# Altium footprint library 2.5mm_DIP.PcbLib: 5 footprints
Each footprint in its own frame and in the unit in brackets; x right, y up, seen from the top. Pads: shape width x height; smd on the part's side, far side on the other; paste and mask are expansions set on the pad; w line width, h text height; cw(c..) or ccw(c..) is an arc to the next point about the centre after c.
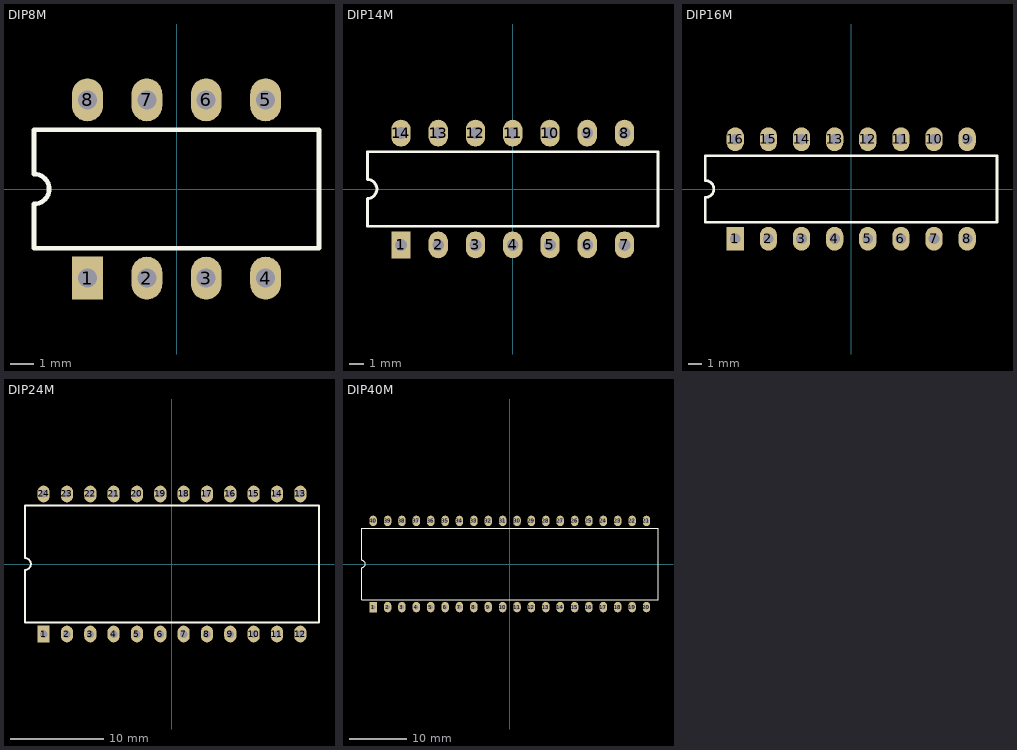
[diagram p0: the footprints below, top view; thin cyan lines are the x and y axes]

## DIP8M [mm] "2.5mm grid"
height 5
pads (8):
  rect 1.3x1.8 hole 0.8: 1(-3.75,-3.75)
  rrect100% 1.3x1.8 hole 0.8: 2(-1.25,-3.75) 3(1.25,-3.75) 4(3.75,-3.75) 5(3.75,3.75) 6(1.25,3.75) 7(-1.25,3.75) 8(-3.75,3.75)
Top Overlay:
  lines w0.2: -6,-2.5 6,-2.5 6,2.5 -6,2.5 -6,0.635 cw(c-6,0) -6,-0.635 -6,-2.5

## DIP14M [mm] "2.5mm grid"
height 5
pads (14):
  rect 1.3x1.8 hole 0.8: 1(-7.5,-3.75)
  rrect100% 1.3x1.8 hole 0.8: 2(-5,-3.75) 3(-2.5,-3.75) 4(0,-3.75) 5(2.5,-3.75) 6(5,-3.75) 7(7.5,-3.75) 8(7.5,3.75) 9(5,3.75) 10(2.5,3.75) 11(0,3.75) 12(-2.5,3.75) 13(-5,3.75) 14(-7.5,3.75)
Top Overlay:
  lines w0.2: -9.75,-2.5 -9.75,-0.635 ccw(c-9.75,0) -9.75,0.635 -9.75,2.5 9.75,2.5 9.75,-2.5 -9.75,-2.5

## DIP16M [mm] "2.5mm grid"
height 5
pads (16):
  rect 1.3x1.8 hole 0.8: 1(-8.75,-3.75)
  rrect100% 1.3x1.8 hole 0.8: 2(-6.25,-3.75) 3(-3.75,-3.75) 4(-1.25,-3.75) 5(1.25,-3.75) 6(3.75,-3.75) 7(6.25,-3.75) 8(8.75,-3.75) 9(8.75,3.75) 10(6.25,3.75) 11(3.75,3.75) 12(1.25,3.75) 13(-1.25,3.75) 14(-3.75,3.75) 15(-6.25,3.75) 16(-8.75,3.75)
Top Overlay:
  lines w0.2: -11,-2.5 -11,-0.635 ccw(c-11,0) -11,0.635 -11,2.5 11,2.5 11,-2.5 -11,-2.5

## DIP24M [mm] "2.5mm grid, 239.24-1, 239.24-2, 239.24-6, 239.24-7"
height 5.5
pads (24):
  rect 1.3x1.8 hole 0.8: 1(-13.75,-7.5)
  rrect100% 1.3x1.8 hole 0.8: 2(-11.25,-7.5) 3(-8.75,-7.5) 4(-6.25,-7.5) 5(-3.75,-7.5) 6(-1.25,-7.5) 7(1.25,-7.5) 8(3.75,-7.5) 9(6.25,-7.5) 10(8.75,-7.5) 11(11.25,-7.5) 12(13.75,-7.5) 13(13.75,7.5) 14(11.25,7.5) 15(8.75,7.5) 16(6.25,7.5) 17(3.75,7.5) 18(1.25,7.5) 19(-1.25,7.5) 20(-3.75,7.5) 21(-6.25,7.5) 22(-8.75,7.5) 23(-11.25,7.5) 24(-13.75,7.5)
Top Overlay:
  lines w0.2: -15.75,-6.25 15.75,-6.25 15.75,6.25 -15.75,6.25 -15.75,0.635 cw(c-15.75,0) -15.75,-0.635 -15.75,-6.25

## DIP40M [mm] "2.5mm grid, 2123.40-1"
height 5.5
pads (40):
  rect 1.3x1.8 hole 0.8: 1(-23.75,-7.5)
  rrect100% 1.3x1.8 hole 0.8: 2(-21.25,-7.5) 3(-18.75,-7.5) 4(-16.25,-7.5) 5(-13.75,-7.5) 6(-11.25,-7.5) 7(-8.75,-7.5) 8(-6.25,-7.5) 9(-3.75,-7.5) 10(-1.25,-7.5) 11(1.25,-7.5) 12(3.75,-7.5) 13(6.25,-7.5) 14(8.75,-7.5) 15(11.25,-7.5) 16(13.75,-7.5) 17(16.25,-7.5) 18(18.75,-7.5) 19(21.25,-7.5) 20(23.75,-7.5) 21(23.75,7.5) 22(21.25,7.5) 23(18.75,7.5) 24(16.25,7.5) 25(13.75,7.5) 26(11.25,7.5) 27(8.75,7.5) 28(6.25,7.5) 29(3.75,7.5) 30(1.25,7.5) 31(-1.25,7.5) 32(-3.75,7.5) 33(-6.25,7.5) 34(-8.75,7.5) 35(-11.25,7.5) 36(-13.75,7.5) 37(-16.25,7.5) 38(-18.75,7.5) 39(-21.25,7.5) 40(-23.75,7.5)
Top Overlay:
  lines w0.2: -25.75,-6.25 -25.75,-0.635 ccw(c-25.75,0) -25.75,0.635 -25.75,6.25 25.75,6.25 25.75,-6.25 -25.75,-6.25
